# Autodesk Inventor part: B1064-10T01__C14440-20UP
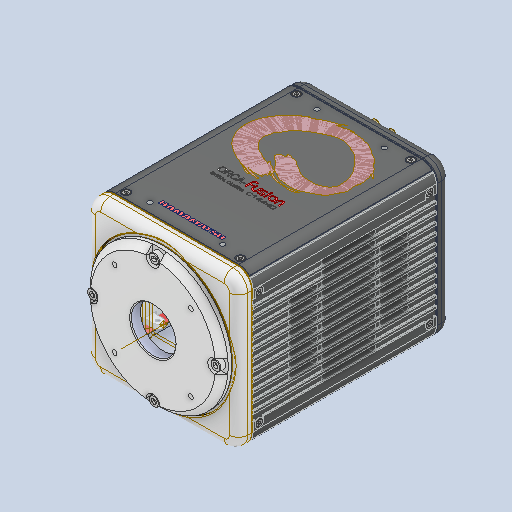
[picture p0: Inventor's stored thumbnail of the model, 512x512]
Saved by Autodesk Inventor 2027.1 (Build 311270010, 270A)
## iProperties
Created: 2019-05
Part Number: B1064-10T01__C14440-20UP
Material: Generic
Description: STEP AP214
Document SubType Name: Modeling
Designer: dunge
Density: 1 g/cm^3
Appearance: Default
Sending System: SolidWorks 2017
Preprocessor: SwSTEP 2.0
Title: B1064-10T01__C14440-20UP.STEP
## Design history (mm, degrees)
feature "20190510__C14440_ORCA-FUSION-1_2:1"
feature "20190510__C14440_ORCA-FUSION-2_3:1"
feature "20190510__C14440_ORCA-FUSION-3_4:1"
feature "20190510__C14440_ORCA-FUSION-4_5:1"
feature "20190510__C14440_ORCA-FUSION-5_6:1"
feature "20190510__C14440_ORCA-FUSION-6_7:1"
feature "20190510__C14440_ORCA-FUSION-7_8:1"
feature "20190510__C14440_ORCA-FUSION-8_9:1"
feature "20190510__C14440_ORCA-FUSION-9_10:1"
feature "20190510__C14440_ORCA-FUSION-10_11:1"
feature "20190510__C14440_ORCA-FUSION-11_12:1"
feature "20190510__C14440_ORCA-FUSION-12_13:1"
feature "20190510__C14440_ORCA-FUSION-13_14:1"
feature "20190510__C14440_ORCA-FUSION-14_15:1"
feature "20190510__C14440_ORCA-FUSION-15_16:1"
feature "20190510__C14440_ORCA-FUSION-16_17:1"
feature "20190510__C14440_ORCA-FUSION-17_18:1"
feature "20190510__C14440_ORCA-FUSION-18_19:1"
feature "20190510__C14440_ORCA-FUSION-19_20:1"
feature "20190510__C14440_ORCA-FUSION-20_21:1"
feature "20190510__C14440_ORCA-FUSION-21_22:1"
feature "20190510__C14440_ORCA-FUSION-22_23:1"
feature "20190510__C14440_ORCA-FUSION-23_24:1"
feature "20190510__C14440_ORCA-FUSION-24_25:1"
feature "20190510__C14440_ORCA-FUSION-25_26:1"
feature "20190510__C14440_ORCA-FUSION-26_27:1"
feature "20190510__C14440_ORCA-FUSION-27_28:1"
feature "20190510__C14440_ORCA-FUSION-28_29:1"
feature "20190510__C14440_ORCA-FUSION-29_30:1"
feature "20190510__C14440_ORCA-FUSION-30_31:1"
feature "20190510__C14440_ORCA-FUSION-31_32:1"
feature "20190510__C14440_ORCA-FUSION-32_33:1"
feature "20190510__C14440_ORCA-FUSION-33_34:1"
feature "20190510__C14440_ORCA-FUSION-34_35:1"
feature "20190510__C14440_ORCA-FUSION-35_36:1"
feature "20190510__C14440_ORCA-FUSION-36_37:1"
feature "20190510__C14440_ORCA-FUSION-37_38:1"
feature "20190510__C14440_ORCA-FUSION-38_39:1"
feature "20190510__C14440_ORCA-FUSION-39_40:1"
feature "20190510__C14440_ORCA-FUSION-40_41:1"
feature "20190510__C14440_ORCA-FUSION-41_42:1"
feature "20190510__C14440_ORCA-FUSION-42_43:1"
feature "20190510__C14440_ORCA-FUSION-43_44:1"
feature "20190510__C14440_ORCA-FUSION-44_45:1"
feature "20190510__C14440_ORCA-FUSION-45_46:1"
feature "20190510__C14440_ORCA-FUSION-46_47:1"
feature "20190510__C14440_ORCA-FUSION-47_48:1"
feature "20190510__C14440_ORCA-FUSION-48_49:1"
feature "20190510__C14440_ORCA-FUSION-49_50:1"
feature "20190510__C14440_ORCA-FUSION-50_51:1"
feature "20190510__C14440_ORCA-FUSION-51_52:1"
feature "20190510__C14440_ORCA-FUSION-52_53:1"
feature "20190510__C14440_ORCA-FUSION-53_54:1"
feature "20190510__C14440_ORCA-FUSION-54_55:1"
feature "20190510__C14440_ORCA-FUSION-55_56:1"
feature "20190510__C14440_ORCA-FUSION-56_57:1"
feature "20190510__C14440_ORCA-FUSION-57_58:1"
feature "20190510__C14440_ORCA-FUSION-58_59:1"
feature "20190510__C14440_ORCA-FUSION-59_60:1"
feature "20190510__C14440_ORCA-FUSION-60_61:1"
feature "20190510__C14440_ORCA-FUSION-61_62:1"
feature "20190510__C14440_ORCA-FUSION-62_63:1"
feature "20190510__C14440_ORCA-FUSION-63_64:1"
feature "20190510__C14440_ORCA-FUSION-64_65:1"
feature "20190510__C14440_ORCA-FUSION-65_66:1"
feature "20190510__C14440_ORCA-FUSION-66_67:1"
feature "20190510__C14440_ORCA-FUSION-67_68:1"
feature "20190510__C14440_ORCA-FUSION-68_69:1"
feature "20190510__C14440_ORCA-FUSION-69_70:1"
feature "20190510__C14440_ORCA-FUSION-70_71:1"
feature "20190510__C14440_ORCA-FUSION-71_72:1"
feature "20190510__C14440_ORCA-FUSION-72_73:1"
feature "20190510__C14440_ORCA-FUSION-73_74:1"
feature "20190510__C14440_ORCA-FUSION-74_75:1"
feature "20190510__C14440_ORCA-FUSION-75_76:1"
feature "20190510__C14440_ORCA-FUSION-76_77:1"
feature "20190510__C14440_ORCA-FUSION-77_78:1"
feature "20190510__C14440_ORCA-FUSION-78_79:1"
feature "20190510__C14440_ORCA-FUSION-79_80:1"
feature "20190510__C14440_ORCA-FUSION-80_81:1"
feature "20190510__C14440_ORCA-FUSION-81_82:1"
feature "20190510__C14440_ORCA-FUSION-82_83:1"
feature "20190510__C14440_ORCA-FUSION-83_84:1"
feature "20190510__C14440_ORCA-FUSION-84_85:1"
feature "20190510__C14440_ORCA-FUSION-85_86:1"
feature "20190510__C14440_ORCA-FUSION-86_87:1"
feature "20190510__C14440_ORCA-FUSION-87_88:1"
feature "20190510__C14440_ORCA-FUSION-88_89:1"
feature "20190510__C14440_ORCA-FUSION-89_90:1"
feature "20190510__C14440_ORCA-FUSION-90_91:1"
feature "20190510__C14440_ORCA-FUSION-91_92:1"
feature "20190510__C14440_ORCA-FUSION-92_93:1"
feature "20190510__C14440_ORCA-FUSION-93_94:1"
feature "20190510__C14440_ORCA-FUSION-94_95:1"
feature "20190510__C14440_ORCA-FUSION-95_96:1"
feature "20190510__C14440_ORCA-FUSION-96_97:1"
feature "20190510__C14440_ORCA-FUSION-97_98:1"
feature "20190510__C14440_ORCA-FUSION-98_99:1"
feature "20190510__C14440_ORCA-FUSION-99_100:1"
feature "20190510__C14440_ORCA-FUSION-100_101:1"
feature "20190510__C14440_ORCA-FUSION-101_102:1"
feature "20190510__C14440_ORCA-FUSION-102_103:1"
feature "20190510__C14440_ORCA-FUSION-103_104:1"
feature "20190510__C14440_ORCA-FUSION-104_105:1"
feature "20190510__C14440_ORCA-FUSION-105_106:1"
feature "20190510__C14440_ORCA-FUSION-106_107:1"
feature "20190510__C14440_ORCA-FUSION-107_108:1"
feature "20190510__C14440_ORCA-FUSION-108_109:1"
feature "20190510__C14440_ORCA-FUSION-109_110:1"
feature "20190510__C14440_ORCA-FUSION-110_111:1"
feature "20190510__C14440_ORCA-FUSION-111_112:1"
feature "20190510__C14440_ORCA-FUSION-112_113:1"
feature "20190510__C14440_ORCA-FUSION-113_114:1"
feature "20190510__C14440_ORCA-FUSION-114_115:1"
feature "20190510__C14440_ORCA-FUSION-115_116:1"
feature "20190510__C14440_ORCA-FUSION-116_117:1"
feature "20190510__C14440_ORCA-FUSION-117_118:1"
feature "20190510__C14440_ORCA-FUSION-118_119:1"
feature "20190510__C14440_ORCA-FUSION-119_120:1"
feature "20190510__C14440_ORCA-FUSION-120_121:1"
feature "20190510__C14440_ORCA-FUSION-121_122:1"
feature "20190510__C14440_ORCA-FUSION-122_123:1"
feature "20190510__C14440_ORCA-FUSION-123_124:1"
feature "20190510__C14440_ORCA-FUSION-124_125:1"
feature "20190510__C14440_ORCA-FUSION-125_126:1"
feature "20190510__C14440_ORCA-FUSION-126_127:1"
feature "20190510__C14440_ORCA-FUSION-127_128:1"
feature "20190510__C14440_ORCA-FUSION-128_129:1"
feature "20190510__C14440_ORCA-FUSION-129_130:1"
feature "20190510__C14440_ORCA-FUSION-130_131:1"
feature "20190510__C14440_ORCA-FUSION-131_132:1"
feature "20190510__C14440_ORCA-FUSION-132_133:1"
feature "20190510__C14440_ORCA-FUSION-133_134:1"
feature "20190510__C14440_ORCA-FUSION-134_135:1"
feature "20190510__C14440_ORCA-FUSION-135_136:1"
feature "20190510__C14440_ORCA-FUSION-136_137:1"
feature "20190510__C14440_ORCA-FUSION-137_138:1"
feature "20190510__C14440_ORCA-FUSION-138_139:1"
feature "20190510__C14440_ORCA-FUSION-139_140:1"
feature "20190510__C14440_ORCA-FUSION-140_141:1"
feature "20190510__C14440_ORCA-FUSION-141_142:1"
feature "20190510__C14440_ORCA-FUSION-142_143:1"
feature "20190510__C14440_ORCA-FUSION-143_144:1"
feature "20190510__C14440_ORCA-FUSION-144_145:1"
feature "20190510__C14440_ORCA-FUSION-145_146:1"
feature "20190510__C14440_ORCA-FUSION-146_147:1"
feature "20190510__C14440_ORCA-FUSION-147_148:1"
feature "20190510__C14440_ORCA-FUSION-148_149:1"
feature "20190510__C14440_ORCA-FUSION-149_150:1"
feature "20190510__C14440_ORCA-FUSION-150_151:1"
feature "20190510__C14440_ORCA-FUSION-151_152:1"
feature "20190510__C14440_ORCA-FUSION-152_153:1"
feature "20190510__C14440_ORCA-FUSION-153_154:1"
feature "20190510__C14440_ORCA-FUSION-154_155:1"
feature "20190510__C14440_ORCA-FUSION-155_156:1"
feature "20190510__C14440_ORCA-FUSION-156_157:1"
feature "Composite1"
workpoint "Work Point1"
  workaxis "Work Axis1"
body "Solid1"
node "Finishes"
body "Solid2"
body "Solid3"
body "Solid4"
body "Solid5"
body "Solid6"
body "Solid7"
body "Solid8"
body "Solid9"
body "Solid10"
body "Solid11"
body "Solid12"
body "Solid13"
body "Solid14"
body "Solid15"
body "Solid16"
body "Solid17"
body "Solid18"
body "Solid19"
body "Solid20"
body "Solid21"
body "Solid22"
body "Solid23"
body "Solid24"
body "Solid25"
body "Solid26"
body "Solid27"
body "Solid28"
body "Solid29"
body "Solid30"
body "Solid31"
body "Solid32"
body "Solid33"
body "Solid34"
body "Solid35"
body "Solid36"
body "Solid37"
body "Solid38"
body "Solid39"
body "Solid40"
body "Solid41"
body "Solid42"
body "Solid43"
body "Solid44"
body "Solid45"
body "Solid46"
body "Solid47"
body "Solid48"
body "Solid49"
body "Solid50"
body "Solid51"
body "Solid52"
body "Solid53"
body "Solid54"
body "Solid55"
body "Solid56"
body "Solid57"
body "Solid58"
body "Solid59"
body "Solid60"
body "Solid61"
body "Solid62"
body "Solid63"
body "Solid64"
body "Solid65"
body "Solid66"
body "Solid67"
body "Solid68"
body "Solid69"
body "Solid70"
body "Solid71"
body "Solid72"
body "Solid73"
body "Solid74"
body "Solid75"
body "Solid76"
body "Solid77"
body "Solid78"
body "Solid79"
body "Solid80"
body "Solid81"
body "Solid82"
body "Solid83"
body "Solid84"
body "Solid85"
body "Solid86"
body "Solid87"
body "Solid88"
body "Solid89"
body "Solid90"
body "Solid91"
body "Solid92"
body "Solid93"
body "Solid94"
body "Solid95"
body "Solid96"
body "Solid97"
body "Solid98"
body "Solid99"
body "Solid100"
body "Solid101"
body "Solid102"
body "Solid103"
body "Solid104"
body "Solid105"
body "Solid106"
body "Solid107"
body "Solid108"
body "Solid109"
body "Solid110"
body "Solid111"
body "Solid112"
body "Solid113"
body "Solid114"
body "Solid115"
body "Solid116"
body "Solid117"
body "Solid118"
body "Solid119"
body "Solid120"
body "Solid121"
body "Solid122"
body "Solid123"
body "Solid124"
body "Solid125"
body "Solid126"
body "Solid127"
body "Solid128"
body "Solid129"
body "Solid130"
body "Solid131"
body "Solid132"
body "Solid133"
body "Solid134"
body "Solid135"
body "Solid136"
body "Solid137"
body "Solid138"
body "Solid139"
body "Solid140"
body "Solid141"
body "Solid142"
body "Solid143"
body "Solid144"
body "Solid145"
body "Solid146"
body "Solid147"
body "Solid148"
body "Solid149"
body "Solid150"
body "Solid151"
body "Solid152"
body "Solid153"
body "Solid154"
body "Solid155"
body "Solid156"
body "Srf1"
node "Finish1" dims "Finish1_Area" = 427.64416
